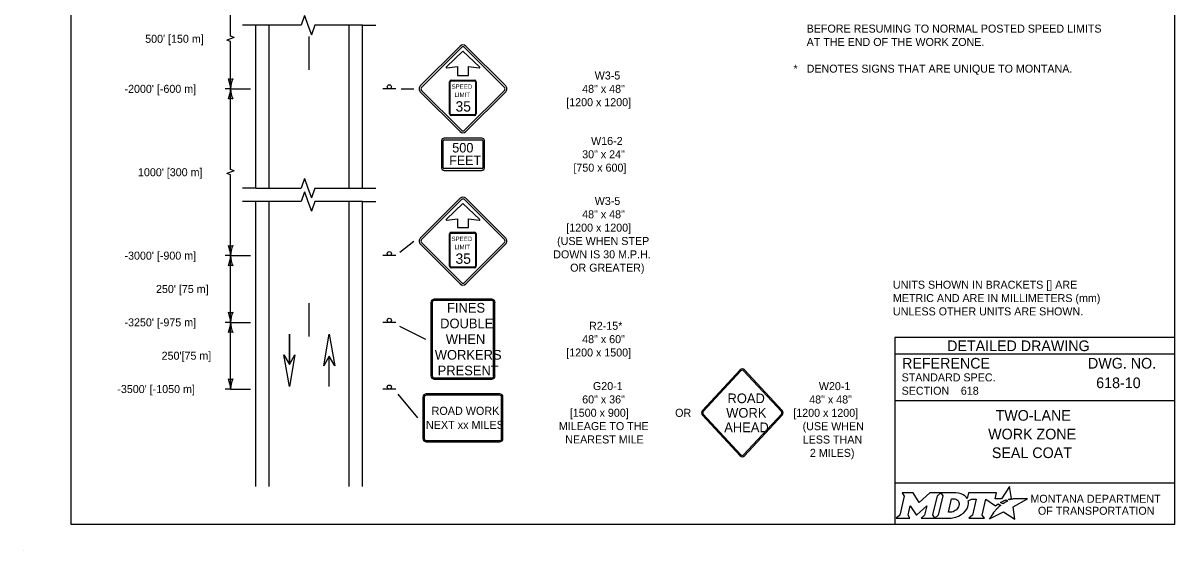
# Model space of a CAD drawing. Extents: x 49991.4 to 50021, y 49987.6 to 50011.4.
# Drawn here: x 49999.98 to 50008.61, y 49999.86 to 50003.82 of the extents above; entities that cross this region are included whole.
import ezdxf

# ---------------------------------------------------------------- set-up
doc = ezdxf.new("R2010")
doc.units = 0
for name, color, linetype in [('Level 1', 7, 'Continuous'), ('Level 2', 7, 'Continuous'), ('Level 3', 7, 'Continuous'), ('Level 6', 7, 'Continuous')]:
    doc.layers.add(name, color=color, linetype=linetype)

msp = doc.modelspace()

# ---------------------------------------------------------------- linework, layer by layer
at = {"layer": 'Level 1'}
for p, q in [((50001.7233, 50002.5814), (50001.7233, 50003.8022)), ((50001.8233, 50002.5814), (50001.8233, 50003.8022)), ((50002.4233, 50002.5814), (50002.4233, 50003.8022)), ((50002.5233, 50002.5814), (50002.5233, 50003.8022)), ((50002.1232, 50003.4683), (50002.1232, 50003.7183)), ((50003.2543, 50003.6461), (50002.955, 50003.3468)), ((50003.2644, 50003.636), (50002.9651, 50003.3367)), ((50003.2757, 50003.6077), (50003.1513, 50003.4904)), ((50003.2543, 50003.6461), (50003.2543, 50003.6461)), ((50003.2644, 50003.636), (50003.2644, 50003.636)), ((50003.4001, 50003.4904), (50003.2757, 50003.6077)), ((50003.5863, 50003.3367), (50003.287, 50003.636)), ((50003.5964, 50003.3468), (50003.2971, 50003.6461)), ((50003.1553, 50003.4817), (50003.2354, 50003.4918)), ((50003.2354, 50003.4918), (50003.2354, 50003.4262)), ((50003.316, 50003.4262), (50003.316, 50003.4918)), ((50003.316, 50003.4918), (50003.396, 50003.4817)), ((50003.2354, 50003.4262), (50003.316, 50003.4262)), ((50002.7712, 50003.3254), (50002.6752, 50003.3254)), ((50002.9651, 50003.3142), (50003.2644, 50003.0149)), ((50003.1753, 50003.1374), (50003.1753, 50003.3787)), ((50003.1805, 50003.1374), (50003.1805, 50003.3787)), ((50003.1878, 50003.3912), (50003.3625, 50003.3912)), ((50003.1878, 50003.386), (50003.3625, 50003.386)), ((50003.2752, 50003.3912), (50003.2752, 50003.3912)), ((50003.287, 50003.0149), (50003.5863, 50003.3142)), ((50003.3698, 50003.3787), (50003.3698, 50003.1374)), ((50003.375, 50003.3787), (50003.375, 50003.1374)), ((50002.955, 50003.3041), (50003.2543, 50003.0048)), ((50003.2971, 50003.0048), (50003.5964, 50003.3041)), ((50003.3625, 50003.1301), (50003.1878, 50003.1301)), ((50003.3625, 50003.1249), (50003.1878, 50003.1249)), ((50003.1144, 50002.9357), (50003.1144, 50002.7341)), ((50003.1278, 50002.7341), (50003.1278, 50002.9357)), ((50003.4168, 50002.9559), (50003.1345, 50002.9559)), ((50003.1345, 50002.9425), (50003.4168, 50002.9425)), ((50003.4235, 50002.9357), (50003.4235, 50002.7341)), ((50003.437, 50002.7341), (50003.437, 50002.9357)), ((50003.4168, 50002.7274), (50003.1345, 50002.7274)), ((50003.1345, 50002.714), (50003.4168, 50002.714)), ((50001.7233, 50000.3459), (50001.7233, 50002.4814)), ((50001.8233, 50000.3459), (50001.8233, 50002.4814)), ((50002.4233, 50000.3459), (50002.4233, 50002.4814)), ((50002.5233, 50000.3459), (50002.5233, 50002.4814)), ((50003.2543, 50002.5051), (50002.955, 50002.2058)), ((50003.2644, 50002.495), (50002.9651, 50002.1957)), ((50003.2757, 50002.4667), (50003.1513, 50002.3494)), ((50003.2543, 50002.5051), (50003.2543, 50002.5051)), ((50003.2644, 50002.495), (50003.2644, 50002.495)), ((50003.4001, 50002.3494), (50003.2757, 50002.4667)), ((50003.5863, 50002.1957), (50003.287, 50002.495)), ((50003.5964, 50002.2058), (50003.2971, 50002.5051)), ((50003.1553, 50002.3407), (50003.2354, 50002.3508)), ((50003.2354, 50002.3508), (50003.2354, 50002.2852)), ((50003.2354, 50002.2852), (50003.316, 50002.2852)), ((50003.316, 50002.2852), (50003.316, 50002.3508)), ((50003.316, 50002.3508), (50003.396, 50002.3407)), ((50003.1753, 50001.9964), (50003.1753, 50002.2377)), ((50003.1805, 50001.9964), (50003.1805, 50002.2377)), ((50003.1878, 50002.2502), (50003.3625, 50002.2502)), ((50003.1878, 50002.245), (50003.3625, 50002.245)), ((50003.2752, 50002.2502), (50003.2752, 50002.2502)), ((50003.3698, 50002.2377), (50003.3698, 50001.9964)), ((50003.375, 50002.2377), (50003.375, 50001.9964)), ((50002.955, 50002.1631), (50003.2543, 50001.8638)), ((50002.9651, 50002.1732), (50003.2644, 50001.8739)), ((50003.287, 50001.8739), (50003.5863, 50002.1732)), ((50003.2971, 50001.8638), (50003.5964, 50002.1631)), ((50002.7712, 50002.0754), (50002.6752, 50002.0754)), ((50003.3625, 50001.9891), (50003.1878, 50001.9891)), ((50003.3625, 50001.9839), (50003.1878, 50001.9839)), ((50002.1232, 50001.4683), (50002.1232, 50001.7183)), ((50003.0357, 50001.7246), (50003.0357, 50001.1746)), ((50003.0457, 50001.7246), (50003.0457, 50001.1746)), ((50003.4907, 50001.7496), (50003.0607, 50001.7496)), ((50003.4907, 50001.7396), (50003.0607, 50001.7396)), ((50003.5057, 50001.1746), (50003.5057, 50001.7246)), ((50003.5157, 50001.1746), (50003.5157, 50001.7246)), ((50002.7712, 50001.5754), (50002.6752, 50001.5754)), ((50001.9732, 50001.4859), (50001.9732, 50001.2601)), ((50001.9735, 50001.4859), (50001.9735, 50001.2601)), ((50002.2729, 50001.0959), (50002.2729, 50001.3217)), ((50002.2732, 50001.0959), (50002.2732, 50001.3217)), ((50003.0607, 50001.1596), (50003.4907, 50001.1596)), ((50003.0607, 50001.1496), (50003.4907, 50001.1496)), ((50005.3538, 50001.2192), (50005.0706, 50000.9152)), ((50005.3603, 50001.2122), (50005.0773, 50000.9081)), ((50005.6631, 50000.9081), (50005.3801, 50001.2122)), ((50005.6697, 50000.9152), (50005.3866, 50001.2192)), ((50002.7712, 50001.0754), (50002.6752, 50001.0754)), ((50002.9757, 50001.0146), (50002.9757, 50000.7046)), ((50002.9857, 50001.0146), (50002.9857, 50000.7046)), ((50003.5507, 50001.0396), (50003.0007, 50001.0396)), ((50003.5507, 50001.0296), (50003.0007, 50001.0296)), ((50003.5657, 50000.7046), (50003.5657, 50001.0146)), ((50003.5757, 50000.7046), (50003.5757, 50001.0146)), ((50005.0706, 50000.8798), (50005.3538, 50000.5758)), ((50005.0773, 50000.8869), (50005.3603, 50000.5828)), ((50005.3801, 50000.5828), (50005.6631, 50000.8869)), ((50005.3866, 50000.5758), (50005.6697, 50000.8798)), ((50003.0007, 50000.6896), (50003.5507, 50000.6896)), ((50003.0007, 50000.6796), (50003.5507, 50000.6796)), ((49999.9766, 49999.8624), (49999.9766, 49999.8624))]:
    msp.add_line(p, q, dxfattribs=at)
for points in [[(50008.6146, 50011.2628), (50000.3356, 50011.2628), (50000.3356, 50000.0624), (50008.6146, 50000.0624)], [(50002.2312, 50001.2495), (50002.2729, 50001.4859), (50002.3148, 50001.2495), (50002.2729, 50001.3217)], [(50002.0152, 50001.3322), (50001.9735, 50001.0959), (50001.9316, 50001.3322), (50001.9735, 50001.2601)]]:
    msp.add_lwpolyline(points, close=True, dxfattribs=at)
for centre in [(50002.7233, 50003.3407), (50002.7233, 50002.0907), (50002.7233, 50001.5907), (50002.7233, 50001.0907)]:
    msp.add_circle(centre, 0.0152, dxfattribs=at)
for centre, radius, start, end in [((50003.2757, 50003.6247), 0.0302, 45.00007, 134.99993), ((50003.2757, 50003.6247), 0.016, 45.00007, 134.99993), ((50003.1548, 50003.4868), 0.00508, 134.62874, 275.82948), ((50003.3965, 50003.4868), 0.00509, 264.38259, 45.16491), ((50002.9764, 50003.3254), 0.0302, 134.99993, 225.00008), ((50002.9764, 50003.3254), 0.016, 134.99993, 225.00008), ((50003.1878, 50003.3787), 0.0125, 90, 180), ((50003.1878, 50003.3787), 0.00728, 90, 180), ((50003.3625, 50003.3787), 0.0125, 360, 90), ((50003.3625, 50003.3787), 0.00728, 360, 90), ((50003.575, 50003.3254), 0.016, 314.99993, 45.00007), ((50003.575, 50003.3254), 0.0302, 314.99993, 45.00008), ((50003.1878, 50003.1374), 0.0125, 180, 270), ((50003.1878, 50003.1374), 0.00728, 180, 270), ((50003.3625, 50003.1374), 0.00728, 270, 360), ((50003.3625, 50003.1374), 0.0125, 270, 360), ((50003.2757, 50003.0261), 0.0302, 225.00007, 314.99993), ((50003.2757, 50003.0261), 0.016, 225.00007, 314.99993), ((50003.1345, 50002.9357), 0.0202, 90, 180), ((50003.1345, 50002.9357), 0.00672, 90, 180), ((50003.4168, 50002.9357), 0.0202, 0, 90), ((50003.4168, 50002.9357), 0.00672, 0, 90), ((50003.1345, 50002.7341), 0.0202, 180, 270), ((50003.1345, 50002.7341), 0.00672, 180, 270), ((50003.4168, 50002.7341), 0.00672, 270, 360), ((50003.4168, 50002.7341), 0.0202, 270, 360), ((50003.2757, 50002.4837), 0.0302, 45.00007, 134.99993), ((50003.2757, 50002.4837), 0.016, 45.00007, 134.99993), ((50003.1548, 50002.3458), 0.00508, 134.62874, 275.82948), ((50003.3965, 50002.3458), 0.00509, 264.38259, 45.16491), ((50002.9764, 50002.1844), 0.0302, 134.99993, 225.00008), ((50002.9764, 50002.1844), 0.016, 134.99993, 225.00008), ((50003.1878, 50002.2377), 0.0125, 90, 180), ((50003.1878, 50002.2377), 0.00728, 90, 180), ((50003.3625, 50002.2377), 0.0125, 360, 90), ((50003.3625, 50002.2377), 0.00728, 360, 90), ((50003.575, 50002.1844), 0.016, 314.99993, 45.00007), ((50003.575, 50002.1844), 0.0302, 314.99993, 45.00008), ((50003.1878, 50001.9964), 0.0125, 180, 270), ((50003.1878, 50001.9964), 0.00728, 180, 270), ((50003.3625, 50001.9964), 0.00728, 270, 360), ((50003.3625, 50001.9964), 0.0125, 270, 360), ((50003.2757, 50001.8851), 0.0302, 225.00007, 314.99993), ((50003.2757, 50001.8851), 0.016, 225.00007, 314.99993), ((50003.0608, 50001.7246), 0.025, 90, 180), ((50003.0608, 50001.7246), 0.015, 90, 180), ((50003.4908, 50001.7246), 0.025, 360, 90), ((50003.4908, 50001.7246), 0.015, 360, 90), ((50003.0608, 50001.1746), 0.025, 180, 270), ((50003.0608, 50001.1746), 0.015, 180, 270), ((50003.4908, 50001.1746), 0.025, 270, 360), ((50003.4908, 50001.1746), 0.015, 270, 360), ((50003.0007, 50001.0146), 0.025, 90, 180), ((50003.0007, 50001.0146), 0.015, 90, 180), ((50003.5507, 50001.0146), 0.025, 0, 90), ((50003.5507, 50001.0146), 0.015, 0, 90), ((50003.0007, 50000.7046), 0.025, 180, 270), ((50003.0007, 50000.7046), 0.015, 180, 270), ((50003.5507, 50000.7046), 0.025, 270, 360), ((50003.5507, 50000.7046), 0.015, 270, 360)]:
    msp.add_arc(centre, radius, start, end, dxfattribs=at)
for centre, major_axis, start_param, end_param in [((50005.3702, 50001.2015), (0, 0.025), 5.497787, 7.068583), ((50005.3702, 50001.2015), (0, 0.015), 5.497787, 7.068583), ((50005.0871, 50000.8974), (0, 0.025), 0.785398, 2.356194), ((50005.0871, 50000.8974), (0, 0.015), 0.785398, 2.356194), ((50005.6533, 50000.8974), (0, 0.015), 3.926991, 5.497791), ((50005.6533, 50000.8974), (0, 0.025), 3.926991, 5.497791), ((50005.3702, 50000.5934), (0, -0.025), 5.497787, 7.068576), ((50005.3702, 50000.5934), (0, -0.015), 5.497787, 7.068576)]:
    msp.add_ellipse(centre, major_axis=major_axis, ratio=0.931, start_param=start_param, end_param=end_param, dxfattribs=at)
at = {"layer": 'Level 2'}
for p, q in [((50008.6146, 50001.4624), (50006.5146, 50001.4624)), ((50006.5146, 50001.4624), (50006.5146, 50000.0624)), ((50008.6146, 50001.3374), (50006.5146, 50001.3374)), ((50008.2507, 50001.1223), (50008.2507, 50001.1223)), ((50008.6146, 50000.9874), (50006.5146, 50000.9874)), ((50007.0089, 50001.0629), (50007.0089, 50001.0629)), ((50007.5646, 50000.7383), (50007.5646, 50000.7383)), ((50008.6146, 50000.3693), (50006.5146, 50000.3693))]:
    msp.add_line(p, q, dxfattribs=at)
for points in [[(50006.5701, 50000.2974), (50006.5842, 50000.274), (50006.5507, 50000.1307), (50006.525, 50000.1082), (50006.6266, 50000.1082), (50006.6131, 50000.131), (50006.6293, 50000.2011), (50006.673, 50000.1321), (50006.6783, 50000.1321), (50006.7534, 50000.2016), (50006.737, 50000.1305), (50006.7123, 50000.1085), (50006.8139, 50000.1085), (50006.8001, 50000.1318), (50006.8333, 50000.2742)], [(50006.8333, 50000.2742), (50006.8586, 50000.2974), (50006.7762, 50000.2974), (50006.6966, 50000.2244), (50006.6521, 50000.2971), (50006.5701, 50000.2974)], [(50006.9722, 50000.2974), (50006.8586, 50000.2974), (50006.8733, 50000.2745), (50006.8394, 50000.1307), (50006.8139, 50000.1085), (50006.9245, 50000.1085)], [(50007.3771, 50000.2447), (50007.3668, 50000.2503), (50007.3784, 50000.2531), (50007.39, 50000.2551), (50007.3726, 50000.3452), (50007.3131, 50000.2539), (50007.2658, 50000.2532), (50007.2761, 50000.2973), (50007.0669, 50000.2974), (50007.0568, 50000.2549), (50007.051, 50000.2632)], [(50006.9962, 50000.2107), (50006.995, 50000.2026), (50006.9918, 50000.1933), (50006.9876, 50000.1851), (50006.982, 50000.1776), (50006.9755, 50000.1707), (50006.9676, 50000.1644), (50006.9593, 50000.1597), (50006.9502, 50000.1558), (50006.9411, 50000.1535), (50006.9319, 50000.1526), (50006.916, 50000.1526), (50006.9396, 50000.2526), (50006.9556, 50000.2526), (50006.9632, 50000.252), (50006.9708, 50000.2501), (50006.9774, 50000.2471), (50006.9835, 50000.2429), (50006.9883, 50000.2379), (50006.992, 50000.2319), (50006.9947, 50000.2257), (50006.9963, 50000.2183), (50006.9963, 50000.2153), (50006.9962, 50000.2107)], [(50007.0636, 50000.2383), (50007.0882, 50000.2514), (50007.1251, 50000.2514), (50007.0965, 50000.1309), (50007.069, 50000.1082), (50007.1852, 50000.1082), (50007.1682, 50000.1311), (50007.1964, 50000.2513), (50007.2677, 50000.1996), (50007.2888, 50000.2147), (50007.3085, 50000.2038)], [(50007.2527, 50000.1479), (50007.2374, 50000.1235), (50007.2327, 50000.116), (50007.2269, 50000.1074), (50007.2246, 50000.1031), (50007.3299, 50000.1562), (50007.4138, 50000.1011), (50007.4007, 50000.1938), (50007.5076, 50000.2522), (50007.4583, 50000.253), (50007.4282, 50000.2534), (50007.4074, 50000.2537), (50007.4006, 50000.2522), (50007.3957, 50000.251), (50007.3873, 50000.2487), (50007.3771, 50000.2447)], [(50007.3267, 50000.2171), (50007.3243, 50000.2154), (50007.306, 50000.225), (50007.3163, 50000.2307), (50007.3204, 50000.2329), (50007.329, 50000.2369), (50007.3347, 50000.2395), (50007.3426, 50000.2425), (50007.3499, 50000.2452), (50007.3617, 50000.2378), (50007.3577, 50000.2357), (50007.3531, 50000.2332), (50007.3489, 50000.231), (50007.3439, 50000.2281), (50007.342, 50000.227), (50007.3393, 50000.2254), (50007.3368, 50000.224), (50007.3345, 50000.2224), (50007.3319, 50000.2206), (50007.3292, 50000.2188), (50007.3267, 50000.2171)], [(50006.9702, 50000.1158), (50006.9786, 50000.1184), (50006.9916, 50000.1238), (50007.012, 50000.1348)], [(50007.2666, 50000.164), (50007.2666, 50000.164)]]:
    msp.add_lwpolyline(points, dxfattribs=at)
for centre, radius, start, end in [((50006.9953, 50000.219), 0.0709, 339.53292, 15.85821), ((50006.9513, 50000.2363), 0.1183, 300.91025, 339.13831)]:
    msp.add_arc(centre, radius, start, end, dxfattribs=at)
for centre, major_axis, ratio, start_param, end_param in [((50006.9701, 50000.25), (0.0834, -0.0037), 0.568097, 0.61298, 1.570796), ((50007.0257, 50000.2573), (0.0361, -0.0295), 0.469099, 1.225588, 1.570796), ((50007.2974, 50000.1941), (-0.0112, -0.0097), 0.021651, 3.157348, 6.283185), ((50006.9248, 50000.2568), (0, 0.1484), 0.987302, 3.139398, 3.456847), ((50007.2597, 50000.1559), (-0.00694, -0.00806), 0.008222, 0, 3.137361), ((50007.2764, 50000.1742), (-0.0098, -0.0102), 0.016458, 3.141593, 6.279097)]:
    msp.add_ellipse(centre, major_axis=major_axis, ratio=ratio, start_param=start_param, end_param=end_param, dxfattribs=at)
at = {"layer": 'Level 3'}
for p, q in [((50001.5332, 50003.7198), (50001.5332, 50004.0754)), ((50001.5332, 50003.7004), (50001.5058, 50003.6908)), ((50001.5332, 50003.681), (50001.5058, 50003.6908)), ((50001.5606, 50003.7102), (50001.5332, 50003.7198)), ((50001.5606, 50003.7102), (50001.5332, 50003.7004)), ((50001.5332, 50003.3254), (50001.5332, 50003.681)), ((50001.5332, 50003.3254), (50001.4932, 50003.3254)), ((50001.5332, 50003.3254), (50001.6832, 50003.3254)), ((50001.5332, 50002.7198), (50001.5332, 50003.3254)), ((50002.8112, 50003.3254), (50002.9061, 50003.3254)), ((50001.5606, 50002.7102), (50001.5332, 50002.7198)), ((50001.5606, 50002.7102), (50001.5332, 50002.7004)), ((50001.5332, 50002.7004), (50001.5058, 50002.6908)), ((50001.5332, 50002.681), (50001.5058, 50002.6908)), ((50001.5332, 50002.0754), (50001.5332, 50002.681)), ((50002.8021, 50002.1009), (50002.9061, 50002.1844)), ((50001.5332, 50002.0754), (50001.4932, 50002.0754)), ((50001.5332, 50001.5754), (50001.5332, 50002.0754)), ((50001.5332, 50002.0754), (50001.6832, 50002.0754)), ((50001.5332, 50001.5754), (50001.4932, 50001.5754)), ((50001.5332, 50001.0754), (50001.5332, 50001.5754)), ((50001.5332, 50001.5754), (50001.6832, 50001.5754)), ((50002.7997, 50001.5474), (50002.9957, 50001.4496)), ((50001.5332, 50001.0754), (50001.4932, 50001.0754)), ((50001.5332, 50001.0754), (50001.6832, 50001.0754)), ((50002.7864, 50001.0384), (50002.9357, 50000.8596))]:
    msp.add_line(p, q, dxfattribs=at)
for centre, radius, start, end in [((50001.5332, 50003.4537), 0.0548, 252.13882, 287.86118), ((50001.3005, 50003.3139), 0.233, 2.82731, 22.07716), ((50001.7554, 50003.3163), 0.2223, 157.45601, 177.63952), ((50001.3111, 50003.3346), 0.2223, 337.45601, 357.63952), ((50001.7659, 50003.3369), 0.233, 182.82731, 202.07716), ((50001.5332, 50003.1972), 0.0548, 72.13882, 107.86118), ((50001.5332, 50002.2037), 0.0548, 252.13882, 287.86118), ((50001.3005, 50002.0639), 0.233, 2.82731, 22.07716), ((50001.7554, 50002.0663), 0.2223, 157.45601, 177.63952), ((50001.3111, 50002.0846), 0.2223, 337.45601, 357.63952), ((50001.7659, 50002.0869), 0.233, 182.82731, 202.07716), ((50001.5332, 50001.9472), 0.0548, 72.13882, 107.86118), ((50001.5332, 50001.7037), 0.0548, 252.13882, 287.86118), ((50001.3005, 50001.5639), 0.233, 2.82731, 22.07716), ((50001.7554, 50001.5663), 0.2223, 157.45601, 177.63952), ((50001.3111, 50001.5846), 0.2223, 337.45601, 357.63952), ((50001.5332, 50001.4472), 0.0548, 72.13882, 107.86118), ((50001.7659, 50001.5869), 0.233, 182.82731, 202.07716), ((50001.5332, 50001.2037), 0.0548, 252.13882, 287.86118), ((50001.3005, 50001.0639), 0.233, 2.82731, 22.07716), ((50001.7554, 50001.0663), 0.2223, 157.45601, 177.63952)]:
    msp.add_arc(centre, radius, start, end, dxfattribs=at)
at = {"layer": 'Level 6'}
for p, q in [((50002.0874, 50003.8753), (50002.0615, 50003.8022)), ((50002.0874, 50003.8753), (50002.1133, 50003.8022)), ((50001.7233, 50003.8022), (50001.6233, 50003.8022)), ((50002.0615, 50003.8022), (50001.7233, 50003.8022)), ((50002.1133, 50003.8022), (50002.1392, 50003.7291)), ((50002.1651, 50003.8022), (50002.1392, 50003.7291)), ((50002.5233, 50003.8022), (50002.1651, 50003.8022)), ((50002.5233, 50003.8022), (50002.6233, 50003.8022)), ((50002.0874, 50002.6545), (50002.0615, 50002.5814)), ((50002.0874, 50002.6545), (50002.1133, 50002.5814)), ((50001.7233, 50002.5814), (50001.6233, 50002.5814)), ((50001.7233, 50002.5814), (50002.0615, 50002.5814)), ((50002.0874, 50002.5545), (50002.0615, 50002.4814)), ((50002.0874, 50002.5545), (50002.1133, 50002.4814)), ((50002.1133, 50002.5814), (50002.1392, 50002.5083)), ((50002.1651, 50002.5814), (50002.1392, 50002.5083)), ((50002.1651, 50002.5814), (50002.5233, 50002.5814)), ((50002.5233, 50002.5814), (50002.6233, 50002.5814)), ((50001.7233, 50002.4814), (50001.6233, 50002.4814)), ((50002.0615, 50002.4814), (50001.7233, 50002.4814)), ((50002.1133, 50002.4814), (50002.1392, 50002.4083)), ((50002.1651, 50002.4814), (50002.1392, 50002.4083)), ((50002.5233, 50002.4814), (50002.1651, 50002.4814)), ((50002.5233, 50002.4814), (50002.6233, 50002.4814))]:
    msp.add_line(p, q, dxfattribs=at)

# ---------------------------------------------------------------- texts
at = {"layer": 'Level 1'}
for s, height, p in [('SPEED', 0.03301, (50003.1898, 50003.3255)), ('LIMIT', 0.03301, (50003.2117, 50003.2645)), ('35', 0.07775, (50003.2197, 50003.155)), ('SPEED', 0.03301, (50003.1898, 50002.1845)), ('LIMIT', 0.03301, (50003.2117, 50002.1235)), ('35', 0.07775, (50003.2197, 50002.014))]:
    msp.add_text(s, height=height, rotation=360, dxfattribs=at).set_placement(p)
for s, height, p in [('500', 0.07124, (50003.1948, 50002.8484)), ('FEET', 0.06989, (50003.1724, 50002.7543)), ('FINES', 0.0725, (50003.156, 50001.6485)), ('DOUBLE', 0.0725, (50003.1045, 50001.531)), ('WHEN', 0.0725, (50003.1465, 50001.4135)), ('WORKERS', 0.0725, (50003.0643, 50001.296)), ('PRESENT', 0.0725, (50003.0857, 50001.1785)), ('ROAD', 0.0725, (50005.2591, 50000.9699)), ('ROAD WORK', 0.0605, (50003.0403, 50000.8823)), ('WORK', 0.0725, (50005.2494, 50000.8612)), ('NEXT xx MILES', 0.0605, (50002.9979, 50000.7768)), ('AHEAD', 0.0725, (50005.2347, 50000.7525))]:
    msp.add_text(s, height=height, dxfattribs=at).set_placement(p)
at = {"layer": 'Level 2'}
for s, height, p in [('BEFORE RESUMING TO NORMAL POSTED SPEED LIMITS ', 0.06, (50005.8528, 50003.7468)), ("500' [150 m]", 0.06, (50000.8925, 50003.6704)), ('AT THE END OF THE WORK ZONE.', 0.06, (50005.8528, 50003.6468)), ('*', 0.06, (50005.7542, 50003.4463)), ('DENOTES SIGNS THAT ARE UNIQUE TO MONTANA.', 0.06, (50005.8528, 50003.4468)), ('W3-5', 0.06, (50004.2635, 50003.3954)), ("-2000' [-600 m]", 0.06, (50000.7374, 50003.2954)), ('48" x 48"', 0.06, (50004.1694, 50003.2954)), ('[1200 x 1200]', 0.06, (50004.05, 50003.1954)), ('W16-2', 0.06, (50004.2363, 50002.9049)), ('30" x 24"', 0.06, (50004.1694, 50002.8049)), ("1000' [300 m]", 0.06, (50000.8386, 50002.6704)), ('[750 x 600]', 0.06, (50004.1039, 50002.7049)), ('W3-5', 0.06, (50004.2635, 50002.4552)), ('48" x 48"', 0.06, (50004.1694, 50002.3552)), ('[1200 x 1200]', 0.06, (50004.05, 50002.2552)), ('(USE WHEN STEP', 0.06, (50003.9814, 50002.1552)), ("-3000' [-900 m]", 0.06, (50000.7374, 50002.0454)), ('DOWN IS 30 M.P.H.', 0.06, (50003.9525, 50002.0552)), ('OR GREATER)', 0.06, (50004.0796, 50001.9552)), ("250' [75 m]", 0.06, (50000.9737, 50001.7954)), ('UNITS SHOWN IN BRACKETS [] ARE ', 0.06, (50006.4997, 50001.8276)), ('METRIC AND ARE IN MILLIMETERS (mm) ', 0.06, (50006.4997, 50001.7276)), ('UNLESS OTHER UNITS ARE SHOWN.', 0.06, (50006.4997, 50001.6276)), ("-3250' [-975 m]", 0.06, (50000.7374, 50001.5454)), ('R2-15*', 0.06, (50004.221, 50001.5196)), ('48" x 60"', 0.06, (50004.1694, 50001.4196)), ('DETAILED DRAWING', 0.0799, (50006.9063, 50001.3599)), ("250'[75 m]", 0.06, (50001.0158, 50001.2954)), ('[1200 x 1500]', 0.06, (50004.05, 50001.3196)), ('REFERENCE', 0.08, (50006.5682, 50001.229)), ('DWG. NO.', 0.08, (50007.9624, 50001.229)), ('STANDARD SPEC.', 0.06, (50006.5649, 50001.133)), ('618-10', 0.08, (50008.0241, 50001.0823)), ("-3500' [-1050 m]", 0.06, (50000.6835, 50001.0456)), ('G20-1', 0.06, (50004.2501, 50001.068)), ('W20-1', 0.06, (50005.9443, 50001.0674)), ('SECTION', 0.06, (50006.5649, 50001.033)), ('618', 0.06, (50007.0089, 50001.0329)), ('60" x 36"', 0.06, (50004.1694, 50000.968)), ('48" x 48"', 0.06, (50005.872, 50000.9674)), ('[1500 x 900]', 0.06, (50004.0769, 50000.868)), ('OR', 0.06, (50004.8665, 50000.8674)), ('[1200 x 1200]', 0.06, (50005.7525, 50000.8674)), ('TWO-LANE', 0.08, (50007.2692, 50000.8383)), ('MILEAGE TO THE', 0.06, (50003.9943, 50000.768)), ('(USE WHEN', 0.06, (50005.8227, 50000.7674)), ('NEAREST MILE', 0.06, (50004.0425, 50000.668)), ('LESS THAN', 0.06, (50005.8233, 50000.6674)), ('WORK ZONE', 0.08, (50007.2139, 50000.6983)), ('SEAL COAT', 0.08, (50007.2417, 50000.5583)), ('2 MILES)', 0.06, (50005.8772, 50000.5674)), ('MONTANA DEPARTMENT', 0.06, (50007.5308, 50000.2236)), ('OF TRANSPORTATION', 0.06, (50007.587, 50000.1336))]:
    msp.add_text(s, height=height, dxfattribs=at).set_placement(p)

doc.saveas('drawing.dxf')
